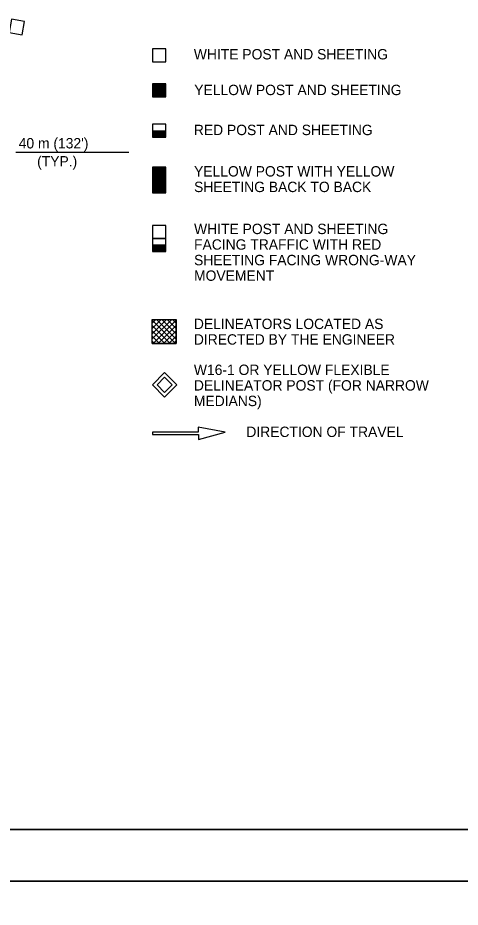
# Model space of a CAD drawing. Extents: x 640253 to 641999, y 298458 to 299646.
# Drawn here: x 641576.3 to 641704.3, y 299044.1 to 299301.1 of the extents above; entities that cross this region are included whole.
import ezdxf

# ---------------------------------------------------------------- set-up
doc = ezdxf.new("R2010")
doc.units = 0
for name, color, linetype in [('1', 7, 'Continuous'), ('2', 7, 'Continuous'), ('PLT-BNDY', 7, 'Continuous')]:
    doc.layers.add(name, color=color, linetype=linetype)

msp = doc.modelspace()

# ---------------------------------------------------------------- linework, layer by layer
at = {"layer": '1'}
for p, q in [((641920.31, 299066.63), (641134.31, 299066.63)), ((641134.31, 299066.63), (641720.31, 299066.63))]:
    msp.add_line(p, q, dxfattribs=at)
at = {"layer": '2'}
for p, q in [((641615.22, 299213.97), (641622.16, 299213.97)), ((641615.22, 299207.03), (641615.22, 299213.97)), ((641622.16, 299213.97), (641622.16, 299213.97)), ((641622.16, 299207.03), (641622.16, 299213.97)), ((641622.16, 299212.98), (641622.16, 299212.98)), ((641622.16, 299211.99), (641622.16, 299211.99)), ((641622.16, 299211), (641622.16, 299211)), ((641622.16, 299210), (641622.16, 299210)), ((641622.16, 299209.01), (641622.16, 299209.01)), ((641622.16, 299208.02), (641622.16, 299208.02)), ((641615.22, 299207.03), (641615.22, 299207.03)), ((641615.22, 299207.03), (641615.22, 299207.03)), ((641615.22, 299207.03), (641615.22, 299207.03)), ((641615.22, 299207.03), (641615.22, 299207.03)), ((641615.22, 299207.03), (641615.22, 299207.03)), ((641615.22, 299207.03), (641615.22, 299207.03)), ((641615.22, 299207.03), (641615.22, 299207.03)), ((641615.22, 299207.03), (641615.22, 299207.03)), ((641615.22, 299207.03), (641615.22, 299207.03)), ((641615.22, 299207.03), (641622.16, 299207.03)), ((641616.21, 299207.03), (641616.21, 299207.03)), ((641617.2, 299207.03), (641617.2, 299207.03)), ((641618.19, 299207.03), (641618.19, 299207.03)), ((641619.2, 299207.03), (641619.2, 299207.03)), ((641620.19, 299207.03), (641620.19, 299207.03)), ((641621.17, 299207.03), (641621.17, 299207.03)), ((641622.16, 299207.03), (641622.16, 299207.03)), ((641622.16, 299207.03), (641622.16, 299207.03)), ((641636.33, 299181.41), (641628.53, 299182.88)), ((641628.53, 299182.88), (641628.53, 299181.44)), ((641628.53, 299181.44), (641615.28, 299181.44)), ((641615.28, 299181.44), (641615.28, 299180.73)), ((641615.28, 299180.73), (641628.61, 299180.73)), ((641628.61, 299179.29), (641636.33, 299181.41)), ((641628.61, 299180.73), (641628.61, 299179.29))]:
    msp.add_line(p, q, dxfattribs=at)
for points in [[(641577.55, 299296.22), (641578.22, 299300.06), (641574.53, 299300.71), (641573.85, 299296.87)], [(641615.25, 299288.42), (641619.15, 299288.42), (641619.15, 299292.16), (641615.25, 299292.16)], [(641615.29, 299237.34), (641619.18, 299237.34), (641619.18, 299241.09), (641615.29, 299241.09)], [(641615.22, 299207.03), (641615.22, 299213.97), (641622.16, 299213.97), (641622.16, 299207.03)], [(641615.22, 299207.03), (641615.22, 299213.97), (641622.16, 299213.97), (641622.16, 299207.03)], [(641618.8, 299191.54), (641615.28, 299195.04), (641618.8, 299198.62), (641622.32, 299195.04)], [(641618.8, 299192.85), (641616.6, 299195.06), (641618.8, 299197.26), (641621.01, 299195.06)]]:
    msp.add_lwpolyline(points, close=True, dxfattribs=at)
for points in [[(641615.29, 299278.28), (641619.19, 299278.28), (641619.19, 299282.03), (641615.29, 299282.03), (641615.29, 299278.28), (641619.13, 299281.96), (641615.35, 299281.96), (641615.35, 299278.33), (641619.13, 299278.33), (641619.13, 299281.89), (641615.43, 299281.89), (641615.43, 299278.4), (641619.05, 299278.4), (641619.04, 299281.8), (641615.5, 299281.8), (641615.5, 299278.46), (641618.98, 299278.46), (641618.98, 299281.74), (641615.57, 299281.74), (641615.57, 299278.52), (641618.9, 299278.52), (641618.89, 299281.67), (641615.64, 299281.67), (641615.63, 299278.57), (641618.83, 299278.59), (641618.81, 299281.6), (641615.7, 299281.6), (641615.69, 299278.64), (641618.77, 299278.66), (641618.75, 299281.53), (641615.77, 299281.53), (641615.75, 299278.72), (641618.68, 299278.74), (641618.68, 299281.44), (641615.86, 299281.45), (641615.82, 299278.77), (641618.58, 299278.82), (641618.59, 299281.38), (641615.94, 299281.38), (641615.9, 299278.84), (641618.5, 299278.88), (641618.5, 299281.32), (641616.02, 299281.31), (641615.98, 299278.88), (641618.41, 299278.95), (641618.41, 299281.25), (641616.1, 299281.22), (641616.06, 299280.12), (641616.06, 299278.95), (641618.34, 299279.02), (641618.31, 299281.15), (641616.18, 299281.11), (641616.14, 299279.02), (641618.25, 299279.09), (641618.22, 299281.07), (641616.29, 299281.01), (641616.25, 299279.11), (641618.12, 299279.16), (641618.1, 299280.94), (641616.43, 299280.91), (641616.37, 299279.24), (641617.98, 299279.27), (641617.95, 299280.84), (641616.58, 299280.78), (641616.51, 299279.35), (641616.51, 299279.35), (641617.83, 299279.4), (641617.82, 299280.69), (641616.72, 299280.65), (641616.65, 299279.48), (641617.67, 299279.54), (641617.68, 299280.54), (641616.85, 299280.52), (641616.82, 299279.64), (641617.52, 299279.67), (641617.49, 299280.41), (641617.02, 299280.38), (641617, 299279.77), (641617.34, 299279.8), (641617.34, 299280.25), (641617.2, 299280.28), (641617.18, 299279.92)], [(641615.29, 299268.49), (641619.18, 299268.49), (641619.18, 299270.36), (641615.29, 299270.36), (641615.29, 299266.62), (641619.18, 299266.62), (641619.18, 299268.41), (641615.36, 299268.41), (641615.36, 299266.67), (641619.12, 299266.67), (641619.12, 299268.34), (641615.43, 299268.34), (641615.43, 299266.74), (641619.04, 299266.74), (641619.04, 299268.27), (641615.5, 299268.27), (641615.5, 299266.82), (641618.96, 299266.82), (641618.96, 299268.19), (641615.58, 299268.19), (641615.58, 299266.9), (641618.87, 299266.9), (641618.87, 299268.11), (641615.66, 299268.11), (641615.65, 299266.98), (641618.78, 299266.98), (641618.77, 299268.02), (641615.74, 299268.02), (641615.75, 299267.05), (641618.7, 299267.05), (641618.7, 299267.94), (641615.83, 299267.94), (641615.83, 299267.15), (641618.59, 299267.15), (641618.59, 299267.84), (641615.93, 299267.84), (641615.93, 299267.24), (641618.48, 299267.24), (641618.47, 299267.75), (641616.02, 299267.75), (641616.02, 299267.34), (641618.37, 299267.34), (641618.37, 299267.63), (641616.13, 299267.63), (641616.13, 299267.44), (641618.25, 299267.44), (641618.25, 299267.53), (641616.22, 299267.54)], [(641608.47, 299262.19), (641575.72, 299262.19)], [(641615.26, 299254.27), (641619.16, 299254.27), (641619.16, 299258.02), (641615.26, 299258.02), (641615.26, 299254.27), (641619.09, 299257.95), (641615.32, 299257.95), (641615.32, 299254.32), (641619.09, 299254.32), (641619.09, 299257.88), (641615.4, 299257.88), (641615.4, 299254.39), (641619.01, 299254.39), (641619.01, 299257.79), (641615.47, 299257.79), (641615.47, 299254.45), (641618.95, 299254.45), (641618.95, 299257.74), (641615.53, 299257.74), (641615.53, 299254.51), (641618.87, 299254.52), (641618.86, 299257.67), (641615.6, 299257.67), (641615.59, 299254.57), (641618.8, 299254.59), (641618.78, 299257.59), (641615.67, 299257.59), (641615.66, 299254.63), (641618.73, 299254.65), (641618.71, 299257.52), (641615.74, 299257.52), (641615.72, 299254.71), (641618.64, 299254.73), (641618.64, 299257.43), (641615.83, 299257.44), (641615.79, 299254.76), (641618.55, 299254.81), (641618.56, 299257.38), (641615.91, 299257.38), (641615.87, 299254.83), (641618.47, 299254.87), (641618.47, 299257.32), (641615.98, 299257.3), (641615.94, 299254.87), (641618.38, 299254.94), (641618.37, 299257.24), (641616.07, 299257.21), (641616.02, 299256.11), (641616.02, 299254.94), (641618.3, 299255.01), (641618.27, 299257.14), (641616.15, 299257.1), (641616.11, 299255.01), (641618.22, 299255.08), (641618.19, 299257.06), (641616.26, 299257), (641616.22, 299255.1), (641618.09, 299255.15), (641618.07, 299256.94), (641616.39, 299256.9), (641616.33, 299255.23), (641617.94, 299255.26), (641617.92, 299256.83), (641616.55, 299256.77), (641616.47, 299255.35), (641616.48, 299255.35), (641617.8, 299255.4), (641617.79, 299256.68), (641616.68, 299256.64), (641616.62, 299255.48), (641617.64, 299255.53), (641617.65, 299256.53), (641616.82, 299256.51), (641616.78, 299255.63), (641617.48, 299255.66), (641617.46, 299256.4), (641616.99, 299256.37), (641616.97, 299255.77), (641617.31, 299255.8), (641617.31, 299256.24), (641617.16, 299256.27), (641617.14, 299255.91)], [(641615.26, 299250.53), (641619.16, 299250.53), (641619.16, 299254.28), (641615.26, 299254.28), (641615.26, 299250.53), (641619.09, 299254.21), (641615.32, 299254.21), (641615.32, 299250.58), (641619.09, 299250.58), (641619.09, 299254.14), (641615.4, 299254.14), (641615.4, 299250.65), (641619.02, 299250.65), (641619.01, 299254.05), (641615.47, 299254.05), (641615.47, 299250.71), (641618.95, 299250.71), (641618.95, 299253.99), (641615.54, 299253.99), (641615.54, 299250.77), (641618.87, 299250.77), (641618.86, 299253.92), (641615.61, 299253.92), (641615.59, 299250.82), (641618.8, 299250.84), (641618.78, 299253.85), (641615.67, 299253.85), (641615.66, 299250.89), (641618.73, 299250.91), (641618.72, 299253.78), (641615.74, 299253.78), (641615.72, 299250.97), (641618.65, 299250.99), (641618.65, 299253.69), (641615.83, 299253.7), (641615.79, 299251.02), (641618.55, 299251.07), (641618.56, 299253.63), (641615.91, 299253.63), (641615.87, 299251.09), (641618.47, 299251.13), (641618.47, 299253.57), (641615.98, 299253.55), (641615.95, 299251.13), (641618.38, 299251.19), (641618.37, 299253.5), (641616.07, 299253.47), (641616.02, 299252.37), (641616.02, 299251.19), (641618.31, 299251.27), (641618.28, 299253.4), (641616.15, 299253.36), (641616.11, 299251.27), (641618.22, 299251.34), (641618.19, 299253.32), (641616.26, 299253.26), (641616.22, 299251.36), (641618.09, 299251.41), (641618.07, 299253.19), (641616.39, 299253.15), (641616.34, 299251.49), (641617.94, 299251.52), (641617.92, 299253.09), (641616.55, 299253.03), (641616.47, 299251.6), (641616.48, 299251.6), (641617.8, 299251.65), (641617.79, 299252.94), (641616.69, 299252.9), (641616.62, 299251.73), (641617.64, 299251.79), (641617.65, 299252.78), (641616.82, 299252.77), (641616.78, 299251.89), (641617.49, 299251.92), (641617.46, 299252.66), (641616.99, 299252.63), (641616.97, 299252.02), (641617.31, 299252.05), (641617.31, 299252.5), (641617.17, 299252.53), (641617.14, 299252.17)], [(641615.26, 299235.48), (641619.16, 299235.48), (641619.16, 299237.36), (641615.26, 299237.36), (641615.26, 299233.61), (641619.16, 299233.61), (641619.16, 299235.4), (641615.33, 299235.4), (641615.33, 299233.67), (641619.09, 299233.67), (641619.09, 299235.33), (641615.41, 299235.33), (641615.41, 299233.73), (641619.01, 299233.73), (641619.01, 299235.26), (641615.48, 299235.26), (641615.48, 299233.81), (641618.93, 299233.81), (641618.93, 299235.18), (641615.55, 299235.18), (641615.55, 299233.89), (641618.84, 299233.89), (641618.84, 299235.1), (641615.63, 299235.1), (641615.63, 299233.97), (641618.75, 299233.97), (641618.75, 299235.01), (641615.72, 299235.01), (641615.72, 299234.04), (641618.67, 299234.04), (641618.67, 299234.93), (641615.81, 299234.93), (641615.81, 299234.14), (641618.57, 299234.14), (641618.56, 299234.83), (641615.9, 299234.83), (641615.9, 299234.23), (641618.45, 299234.23), (641618.45, 299234.74), (641616, 299234.74), (641616, 299234.33), (641618.34, 299234.33), (641618.34, 299234.62), (641616.11, 299234.62), (641616.11, 299234.43), (641618.23, 299234.43), (641618.23, 299234.52), (641616.19, 299234.53)], [(641615.22, 299208.33), (641620.86, 299213.97)], [(641615.22, 299209.86), (641619.34, 299213.97)], [(641615.22, 299211.37), (641617.82, 299213.97)], [(641615.22, 299212.89), (641616.3, 299213.97)], [(641621.92, 299207.03), (641615.22, 299213.73)], [(641615.45, 299207.03), (641622.16, 299213.74)], [(641622.16, 299208.29), (641616.49, 299213.97)], [(641622.16, 299209.82), (641618.02, 299213.97)], [(641622.16, 299211.35), (641619.54, 299213.97)], [(641622.16, 299212.86), (641621.05, 299213.97)], [(641620.39, 299207.03), (641615.22, 299212.2)], [(641618.89, 299207.03), (641615.22, 299210.69)], [(641616.96, 299207.03), (641622.16, 299212.23)], [(641618.49, 299207.03), (641622.16, 299210.71)], [(641617.36, 299207.03), (641615.22, 299209.16)], [(641620.01, 299207.03), (641622.16, 299209.18)], [(641615.83, 299207.03), (641615.22, 299207.63)], [(641621.52, 299207.03), (641622.15, 299207.65)]]:
    msp.add_lwpolyline(points, dxfattribs=at)
at = {"layer": 'PLT-BNDY'}
for points in [[(641094.31, 299645.63), (641935.31, 299645.63), (641935.31, 299051.63), (641094.31, 299051.63)], [(641094.31, 299051.63), (641935.31, 299051.63), (641935.31, 298457.63), (641094.31, 298457.63)]]:
    msp.add_lwpolyline(points, close=True, dxfattribs=at)

# ---------------------------------------------------------------- texts
at = {"layer": '2'}
for s, p in [('WHITE POST AND SHEETING', (641627.25, 299289.11)), ('YELLOW POST AND SHEETING', (641627.37, 299278.79)), ('RED POST AND SHEETING', (641627.26, 299267.23)), ("40 m (132')", (641576.59, 299263.39)), ('(TYP.)', (641581.92, 299258.17)), ('YELLOW POST WITH YELLOW', (641627.32, 299255.27)), ('SHEETING BACK TO BACK', (641627.32, 299250.77)), ('WHITE POST AND SHEETING', (641627.32, 299238.63)), ('FACING TRAFFIC WITH RED ', (641627.32, 299234.13)), ('SHEETING FACING WRONG-WAY', (641627.32, 299229.63)), ('MOVEMENT', (641627.32, 299225.13)), ('DELINEATORS LOCATED AS', (641627.26, 299211.19)), ('DIRECTED BY THE ENGINEER', (641627.26, 299206.69)), ('W16-1 OR YELLOW FLEXIBLE', (641627.27, 299197.92)), ('DELINEATOR POST (FOR NARROW', (641627.27, 299193.42)), ('MEDIANS)', (641627.27, 299188.92)), ('DIRECTION OF TRAVEL', (641642.44, 299180))]:
    msp.add_text(s, height=3, dxfattribs=at).set_placement(p)

doc.saveas('drawing.dxf')
